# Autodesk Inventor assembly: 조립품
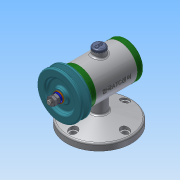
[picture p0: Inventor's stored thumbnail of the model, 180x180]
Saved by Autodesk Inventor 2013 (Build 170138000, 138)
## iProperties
Created: 2018-12
Part Number: 조립품
Document SubType Name: Assembly
Designer: Administrator
Author: Administrator
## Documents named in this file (15)
- C:\Users\Administrator\Desktop\481207V1046\조립품.iam
- C:\Users\Administrator\Desktop\481207V1046\본체.ipt
- C:\Users\Administrator\Desktop\481207V1046\축.ipt
- C:\Users\Administrator\Desktop\481207V1046\키 3 x 3 x 12.ipt
- C:\Users\Administrator\Desktop\481207V1046\베어링 15 x 32 x 9.ipt
- C:\Users\Administrator\Desktop\481207V1046\뒤커버.ipt
- C:\Users\Administrator\Desktop\481207V1046\앞커버.ipt
- C:\Users\Administrator\Desktop\481207V1046\오일 실 15 25 7.ipt
- C:\Users\Administrator\Desktop\481207V1046\V벨트풀리.ipt
- C:\Users\Administrator\Desktop\481207V1046\와셔 8x17.ipt
- C:\Users\Administrator\Desktop\481207V1046\스프링와셔 8.ipt
- C:\Users\Administrator\Desktop\481207V1046\너트 M8.ipt
- 너트 M8.ipt
- C:\Users\Administrator\Desktop\481207V1046\고무캡.ipt
- C:\Users\Administrator\Desktop\481207V1046\볼트 M4 x 12.ipt
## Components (2 placed, 2 different names)
1. V벨트풀리:1
2. 고무캡:1
